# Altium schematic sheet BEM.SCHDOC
size A4
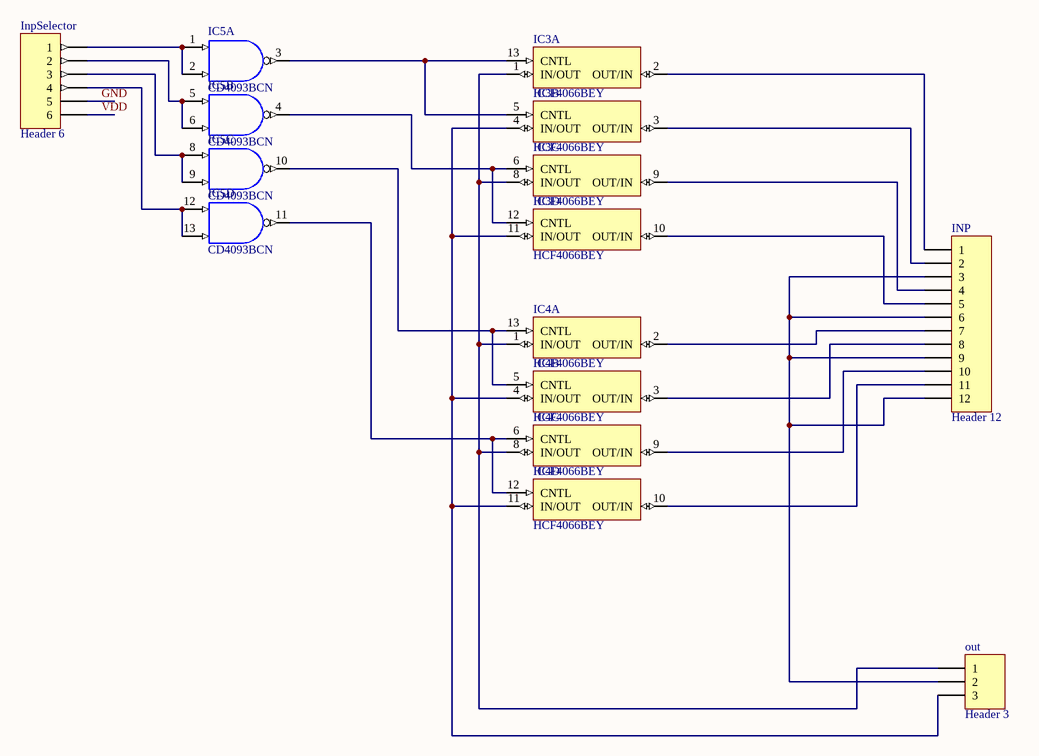
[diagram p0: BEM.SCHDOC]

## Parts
IC3  HCF4066BEY  [DIP14]  (parts A,B,C,D of 4)
IC4  HCF4066BEY  [DIP14]  (parts A,B,C,D of 4)
IC5  CD4093BCN  [N14A]  (parts A,B,C,D of 4)
INP  Header 12  [HDR1X12]
InpSelector  Header 6  [HDR1X6]
out  Header 3  [HDR1X3]

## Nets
GND: IC3.7(GND) IC4.7(GND) IC5.7(GND) InpSelector.5
VCC: IC5.14(VCC)
VDD: IC3.14(VDD) IC4.14(VDD) InpSelector.6
NetIC3_1: IC3.1(IN/OUT) IC3.8(IN/OUT) IC4.1(IN/OUT) IC4.8(IN/OUT) out.1
NetIC3_2: IC3.2(OUT/IN) INP.1
NetIC3_3: IC3.3(OUT/IN) INP.2
NetIC3_4: IC3.4(IN/OUT) IC3.11(IN/OUT) IC4.4(IN/OUT) IC4.11(IN/OUT) out.3
NetIC3_5: IC3.5(CNTL) IC3.13(CNTL) IC5.3(J)
NetIC3_6: IC3.6(CNTL) IC3.12(CNTL) IC5.4(K)
NetIC3_9: IC3.9(OUT/IN) INP.4
NetIC3_10: IC3.10(OUT/IN) INP.5
NetIC4_2: IC4.2(OUT/IN) INP.7
NetIC4_3: IC4.3(OUT/IN) INP.8
NetIC4_5: IC4.5(CNTL) IC4.13(CNTL) IC5.10(L)
NetIC4_6: IC4.6(CNTL) IC4.12(CNTL) IC5.11(M)
NetIC4_9: IC4.9(OUT/IN) INP.10
NetIC4_10: IC4.10(OUT/IN) INP.11
NetIC5_1: IC5.1(A) IC5.2(B) InpSelector.1
NetIC5_5: IC5.5(C) IC5.6(D) InpSelector.2
NetIC5_8: IC5.8(E) IC5.9(F) InpSelector.3
NetIC5_12: IC5.12(G) IC5.13(H) InpSelector.4
NetINP_3: INP.3 INP.6 INP.9 INP.12 out.2

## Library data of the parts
IC3 IC4 = HCF4066BEY: Quad Bilateral Switch For Transmission or Multiplexing of Analog or Digital Signals; Package Information: Latest Revision: Jan-1997
IC5 = CD4093BCN: Quad 2-Input NAND Schmitt Trigger; Package Information: Latest Revision: 2000
INP = Header 12: Header, 12-Pin
InpSelector = Header 6: Header, 6-Pin
out = Header 3: Header, 3-Pin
